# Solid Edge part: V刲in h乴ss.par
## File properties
Author: Türk
Template: Iso Part.par
Last saved by: Türk
Revision: 8
Application: Solid Edge
Accuracy: 0,990
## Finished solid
Body 1: sheet body, 2 faces, 20 edges, 20 vertices.
  Faces by surface: plane 2
  Edges by curve: line 20
Body 2: solid body, 10 faces, 10 edges, 0 vertices.
  Faces by surface: cylinder 4, plane 4, cone 2
  Edges by curve: circle 10
Bounding box of the edges (mm): 50.000 x 80.000 x 80.000, from (0, -40, -40) to (50, 40, 40).
Cylindrical faces by radius (mm): R35 x2, R37.5 x1, R40 x1
Conical faces (half-angle, radius in mm at the cone's reference point): 45 deg R39 x1, 45 deg R40 x1
Planar faces by outward normal: +x 2, -x 2
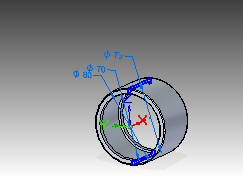
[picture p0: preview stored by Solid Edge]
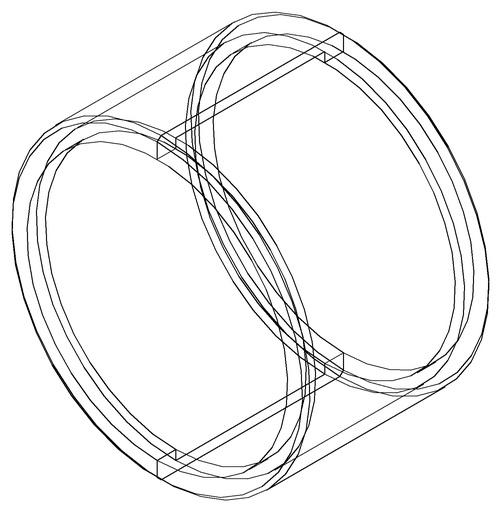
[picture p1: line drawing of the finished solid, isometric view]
